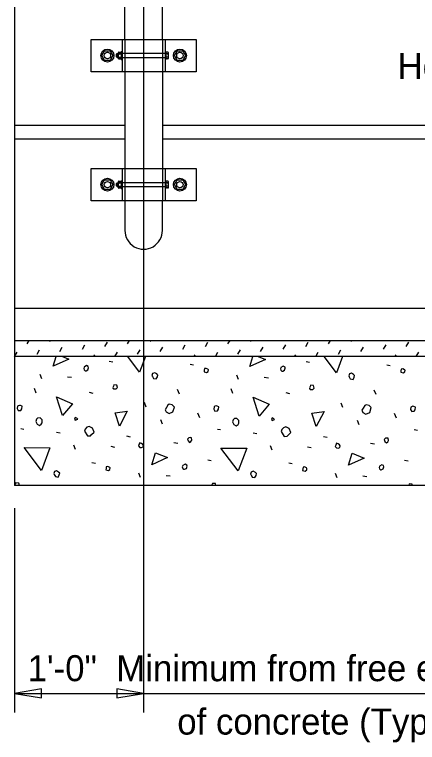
# Model space of a CAD drawing. Extents: x 0 to 41, y -96 to 25.
# Drawn here: x 3.62 to 6.74, y -84.64 to -79.01 of the extents above; entities that cross this region are included whole.
import ezdxf

# ---------------------------------------------------------------- set-up
doc = ezdxf.new("R2010")
doc.units = 0
for name, color, linetype in [('CL_Major', 7, 'Continuous'), ('Dimension', 7, 'Continuous'), ('Miscellaneous', 7, 'Continuous'), ('SteelMisc', 7, 'Continuous'), ('SteelMisc_h', 7, 'Continuous'), ('SupstrConc', 7, 'Continuous'), ('SupstrConc_h', 7, 'Continuous'), ('TextStructures', 7, 'Continuous')]:
    doc.layers.add(name, color=color, linetype=linetype)

msp = doc.modelspace()

# ---------------------------------------------------------------- linework, layer by layer
at = {"layer": 'CL_Major'}
msp.add_line((4.615, -70.4949), (4.615, -84.4122), dxfattribs=at)
at = {"layer": 'Dimension'}
for p, q in [((3.615, -82.8281), (3.615, -84.4122)), ((3.6151, -84.2642), (8.3895, -84.2642))]:
    msp.add_line(p, q, dxfattribs=at)
for points in [[(3.6151, -84.2641), (3.8233, -84.2994), (3.8233, -84.2288)], [(4.6151, -84.2641), (4.4068, -84.2288), (4.4068, -84.2993)]]:
    msp.add_lwpolyline(points, close=True, dxfattribs=at)
at = {"layer": 'Miscellaneous'}
for p, q in [((4.4075, -79.3301), (4.4075, -79.318)), ((4.4132, -79.3301), (4.4132, -79.318)), ((4.4075, -80.3301), (4.4075, -80.318)), ((4.4132, -80.3301), (4.4132, -80.318)), ((3.7123, -81.5575), (3.7283, -81.5298)), ((3.8873, -81.5381), (3.8921, -81.5298)), ((4.4901, -81.5575), (4.5062, -81.5298)), ((4.6651, -81.5381), (4.6699, -81.5298)), ((5.2679, -81.5575), (5.284, -81.5298)), ((5.4429, -81.5381), (5.4477, -81.5298)), ((6.0457, -81.5575), (6.0618, -81.5298)), ((6.2207, -81.5381), (6.2255, -81.5298)), ((3.9651, -81.6158), (3.9845, -81.5823)), ((4.1401, -81.5964), (4.1595, -81.5628)), ((4.3151, -81.577), (4.3345, -81.5434)), ((4.7429, -81.6158), (4.7623, -81.5823)), ((4.9179, -81.5964), (4.9373, -81.5628)), ((5.0929, -81.577), (5.1123, -81.5434)), ((5.5207, -81.6158), (5.5401, -81.5823)), ((5.6957, -81.5964), (5.7152, -81.5628)), ((5.8707, -81.577), (5.8902, -81.5434)), ((6.2985, -81.6158), (6.318, -81.5823)), ((6.4735, -81.5964), (6.493, -81.5628)), ((6.6485, -81.577), (6.668, -81.5434)), ((3.615, -81.6547), (3.6345, -81.6211)), ((3.7901, -81.6353), (3.8095, -81.6017)), ((4.2291, -81.6547), (4.2373, -81.6406)), ((4.3929, -81.6547), (4.4123, -81.6211)), ((4.5679, -81.6353), (4.5873, -81.6017)), ((5.0069, -81.6547), (5.0151, -81.6406)), ((5.1707, -81.6547), (5.1901, -81.6211)), ((5.3457, -81.6353), (5.3651, -81.6017)), ((5.7847, -81.6547), (5.7929, -81.6406)), ((5.9485, -81.6547), (5.9679, -81.6211)), ((6.1235, -81.6353), (6.143, -81.6017)), ((6.5626, -81.6547), (6.5708, -81.6406)), ((6.7263, -81.6547), (6.7458, -81.6211)), ((4.3489, -81.6901), (4.3754, -81.6954)), ((5.8727, -81.6936), (5.8992, -81.6989)), ((4.9746, -81.7148), (5.0012, -81.7201)), ((6.4985, -81.7184), (6.525, -81.7237)), ((3.8256, -81.828), (3.8132, -81.7944)), ((4.0254, -81.8121), (4.0572, -81.8156)), ((5.3494, -81.8315), (5.337, -81.7979)), ((5.5492, -81.8156), (5.581, -81.8191)), ((3.7832, -81.9376), (3.769, -81.9022)), ((4.8916, -81.9464), (4.8774, -81.9111)), ((5.307, -81.9411), (5.2928, -81.9058)), ((6.4154, -81.9499), (6.4012, -81.9146)), ((4.1933, -81.9305), (4.2216, -81.9376)), ((5.7171, -81.934), (5.7454, -81.9411)), ((4.6352, -82.0472), (4.6211, -82.0118)), ((6.1591, -82.0507), (6.1449, -82.0154)), ((5.0489, -82.1285), (5.0348, -82.0931)), ((4.7607, -82.1798), (4.7484, -82.1462)), ((6.2846, -82.1833), (6.2722, -82.1497)), ((6.5727, -82.132), (6.5586, -82.0967)), ((3.663, -82.2133), (3.6877, -82.2169)), ((3.9387, -82.2416), (3.9688, -82.2469)), ((5.1868, -82.2169), (5.2115, -82.2204)), ((5.4626, -82.2452), (5.4926, -82.2505)), ((6.7106, -82.2204), (6.7353, -82.224)), ((4.4832, -82.2699), (4.5115, -82.277)), ((6.007, -82.2735), (6.0353, -82.2805)), ((4.0872, -82.376), (4.0749, -82.3424)), ((4.3612, -82.3495), (4.3895, -82.3565)), ((4.8491, -82.3212), (4.8792, -82.3265)), ((5.611, -82.3795), (5.5987, -82.3459)), ((5.885, -82.353), (5.9133, -82.3601)), ((6.373, -82.3247), (6.403, -82.33)), ((3.615, -82.4555), (3.6152, -82.4555)), ((4.2145, -82.475), (4.241, -82.4803)), ((5.1125, -82.4538), (5.1391, -82.4591)), ((5.7383, -82.4785), (5.7648, -82.4838)), ((6.6363, -82.4573), (6.6629, -82.4626)), ((4.5893, -82.5916), (4.5769, -82.5581)), ((4.789, -82.5757), (4.8209, -82.5793)), ((6.1131, -82.5952), (6.1007, -82.5616)), ((6.3128, -82.5793), (6.3447, -82.5828))]:
    msp.add_line(p, q, dxfattribs=at)
for points in [[(3.914, -81.729), (3.9368, -81.6547)], [(3.9869, -81.6547), (4.036, -81.6742), (3.914, -81.729)], [(4.584, -81.7767), (4.4913, -81.6547)], [(4.6296, -81.6547), (4.584, -81.7767)], [(5.4378, -81.7325), (5.4617, -81.6547)], [(5.5018, -81.6547), (5.5598, -81.6777), (5.4378, -81.7325)], [(6.1078, -81.7802), (6.0124, -81.6547)], [(6.1547, -81.6547), (6.1078, -81.7802)], [(4.1615, -81.7643), (4.1685, -81.7643), (4.1827, -81.7573), (4.188, -81.7414), (4.1862, -81.7325), (4.1721, -81.7254), (4.1544, -81.736), (4.1509, -81.7467), (4.1544, -81.7573), (4.1615, -81.7643)], [(5.0825, -81.7732), (5.1019, -81.7785), (5.1143, -81.7696), (5.1161, -81.7573), (5.1125, -81.7537), (5.0984, -81.7467), (5.086, -81.7484), (5.0843, -81.7608), (5.0825, -81.7732)], [(5.6853, -81.7679), (5.6924, -81.7679), (5.7065, -81.7608), (5.7118, -81.7449), (5.71, -81.736), (5.6959, -81.729), (5.6782, -81.7396), (5.6747, -81.7502), (5.6782, -81.7608), (5.6853, -81.7679)], [(6.6063, -81.7767), (6.6257, -81.782), (6.6381, -81.7732), (6.6399, -81.7608), (6.6363, -81.7573), (6.6222, -81.7502), (6.6098, -81.752), (6.6081, -81.7643), (6.6063, -81.7767)], [(4.683, -81.8085), (4.6918, -81.8244), (4.713, -81.828), (4.7219, -81.8121), (4.7254, -81.7979), (4.7166, -81.7891), (4.7006, -81.7802), (4.6847, -81.7855), (4.6794, -81.8015), (4.683, -81.8085)], [(6.2068, -81.8121), (6.2156, -81.828), (6.2368, -81.8315), (6.2457, -81.8156), (6.2492, -81.8015), (6.2404, -81.7926), (6.2245, -81.7838), (6.2086, -81.7891), (6.2032, -81.805), (6.2068, -81.8121)], [(4.3807, -81.9058), (4.4019, -81.9058), (4.4125, -81.8951), (4.4072, -81.8757), (4.3842, -81.8739), (4.3807, -81.8845), (4.3754, -81.8934), (4.3807, -81.9058), (4.3771, -81.9022)], [(5.9045, -81.9093), (5.9257, -81.9093), (5.9363, -81.8987), (5.931, -81.8792), (5.908, -81.8775), (5.9045, -81.8881), (5.8992, -81.8969), (5.9045, -81.9093), (5.901, -81.9058)], [(3.9865, -82.1126), (3.9387, -81.9659), (4.0642, -82.0207), (3.9865, -82.1126)], [(5.5103, -82.1161), (5.4626, -81.9694), (5.5881, -82.0242), (5.5103, -82.1161)], [(3.6347, -82.0578), (3.6435, -82.0737), (3.663, -82.0719), (3.6718, -82.0596), (3.6736, -82.0401), (3.6612, -82.0348), (3.6524, -82.033), (3.6418, -82.0366), (3.6382, -82.0401), (3.6347, -82.0578)], [(4.789, -82.0843), (4.812, -82.0967), (4.8421, -82.0843), (4.8544, -82.0472), (4.8368, -82.0295), (4.8138, -82.0242), (4.8032, -82.0313), (4.7908, -82.0507), (4.782, -82.0666), (4.789, -82.0843)], [(5.1585, -82.0613), (5.1673, -82.0772), (5.1868, -82.0755), (5.1956, -82.0631), (5.1974, -82.0436), (5.185, -82.0383), (5.1762, -82.0366), (5.1656, -82.0401), (5.162, -82.0436), (5.1585, -82.0613)], [(6.3128, -82.0878), (6.3358, -82.1002), (6.3659, -82.0878), (6.3783, -82.0507), (6.3606, -82.033), (6.3376, -82.0277), (6.327, -82.0348), (6.3146, -82.0542), (6.3058, -82.0702), (6.3128, -82.0878)], [(4.4284, -82.1939), (4.3948, -82.0896), (4.4885, -82.0772), (4.4284, -82.1939)], [(5.9522, -82.1974), (5.9186, -82.0931), (6.0123, -82.0808), (5.9522, -82.1974)], [(6.6823, -82.0649), (6.6912, -82.0808), (6.7106, -82.079), (6.7194, -82.0666), (6.7212, -82.0472), (6.7088, -82.0419), (6.7, -82.0401), (6.6894, -82.0436), (6.6858, -82.0472), (6.6823, -82.0649)], [(3.7796, -82.1568), (3.7902, -82.178), (3.8079, -82.1886), (3.8221, -82.178), (3.8291, -82.1674), (3.8291, -82.1462), (3.8132, -82.1303), (3.7938, -82.132), (3.7849, -82.1409), (3.7796, -82.1568)], [(4.0855, -82.1479), (4.1049, -82.1391), (4.0978, -82.132), (4.0855, -82.1267), (4.0802, -82.1391), (4.0855, -82.1479)], [(5.3035, -82.1603), (5.3141, -82.1815), (5.3317, -82.1921), (5.3459, -82.1815), (5.353, -82.1709), (5.353, -82.1497), (5.337, -82.1338), (5.3176, -82.1356), (5.3088, -82.1444), (5.3035, -82.1603)], [(5.6093, -82.1515), (5.6287, -82.1426), (5.6217, -82.1356), (5.6093, -82.1303), (5.604, -82.1426), (5.6093, -82.1515)], [(4.1562, -82.2328), (4.1792, -82.2699), (4.2021, -82.2681), (4.211, -82.2593), (4.2304, -82.2399), (4.218, -82.2098), (4.1933, -82.1957), (4.1756, -82.2027), (4.1615, -82.2169), (4.1562, -82.2328)], [(5.68, -82.2363), (5.703, -82.2735), (5.7259, -82.2717), (5.7348, -82.2628), (5.7542, -82.2434), (5.7419, -82.2133), (5.7171, -82.1992), (5.6994, -82.2063), (5.6853, -82.2204), (5.68, -82.2363)], [(4.9605, -82.3088), (4.9711, -82.3194), (4.9817, -82.3123), (4.9888, -82.3017), (4.9853, -82.2841), (4.9764, -82.2823), (4.964, -82.2841), (4.9534, -82.2947), (4.9605, -82.3088)], [(6.4843, -82.3123), (6.4949, -82.3229), (6.5055, -82.3159), (6.5126, -82.3053), (6.5091, -82.2876), (6.5002, -82.2858), (6.4879, -82.2876), (6.4773, -82.2982), (6.4843, -82.3123)], [(3.8238, -82.5368), (3.6895, -82.3601), (3.8892, -82.3618), (3.8238, -82.5368)], [(4.5857, -82.3583), (4.5981, -82.3601), (4.6105, -82.3548), (4.614, -82.3442), (4.6087, -82.3353), (4.5981, -82.3283), (4.5857, -82.3229), (4.5787, -82.3371), (4.5751, -82.3477), (4.5857, -82.3583)], [(5.3476, -82.5404), (5.2133, -82.3636), (5.4131, -82.3654), (5.3476, -82.5404)], [(6.1096, -82.3618), (6.1219, -82.3636), (6.1343, -82.3583), (6.1378, -82.3477), (6.1325, -82.3389), (6.1219, -82.3318), (6.1096, -82.3265), (6.1025, -82.3406), (6.0989, -82.3512), (6.1096, -82.3618)], [(4.6777, -82.4927), (4.7059, -82.4007), (4.7996, -82.4379), (4.6777, -82.4927)], [(6.2015, -82.4962), (6.2298, -82.4043), (6.3235, -82.4414), (6.2015, -82.4962)], [(4.9252, -82.528), (4.9322, -82.528), (4.9464, -82.5209), (4.9517, -82.505), (4.9499, -82.4962), (4.9358, -82.4891), (4.9181, -82.4997), (4.9145, -82.5103), (4.9181, -82.5209), (4.9252, -82.528)], [(3.9228, -82.5687), (3.9317, -82.5846), (3.9529, -82.5881), (3.9617, -82.5722), (3.9653, -82.5581), (3.9564, -82.5492), (3.9405, -82.5404), (3.9246, -82.5457), (3.9193, -82.5616), (3.9228, -82.5687)], [(4.3223, -82.5333), (4.3418, -82.5386), (4.3542, -82.5298), (4.3559, -82.5174), (4.3524, -82.5139), (4.3383, -82.5068), (4.3259, -82.5086), (4.3241, -82.5209), (4.3223, -82.5333)], [(5.4466, -82.5722), (5.4555, -82.5881), (5.4767, -82.5916), (5.4855, -82.5757), (5.4891, -82.5616), (5.4802, -82.5528), (5.4643, -82.5439), (5.4484, -82.5492), (5.4431, -82.5651), (5.4466, -82.5722)], [(5.8462, -82.5368), (5.8656, -82.5422), (5.878, -82.5333), (5.8797, -82.5209), (5.8762, -82.5174), (5.8621, -82.5103), (5.8497, -82.5121), (5.8479, -82.5245), (5.8462, -82.5368)], [(6.449, -82.5315), (6.456, -82.5315), (6.4702, -82.5245), (6.4755, -82.5086), (6.4737, -82.4997), (6.4596, -82.4927), (6.4419, -82.5033), (6.4384, -82.5139), (6.4419, -82.5245), (6.449, -82.5315)], [(3.6522, -82.6547), (3.6471, -82.6358), (3.6241, -82.6341), (3.6205, -82.6447), (3.6152, -82.6535), (3.6158, -82.6547)], [(5.1751, -82.6547), (5.1709, -82.6394), (5.1479, -82.6376), (5.1444, -82.6482), (5.1404, -82.6547)], [(6.6979, -82.6547), (6.6947, -82.6429), (6.6717, -82.6411), (6.6682, -82.6518), (6.6664, -82.6547)]]:
    msp.add_lwpolyline(points, dxfattribs=at)
at = {"layer": 'SteelMisc'}
for p, q in [((4.4692, -79.1982), (4.4692, -78.7223)), ((4.7609, -79.1982), (4.7609, -78.7223)), ((4.2091, -79.1982), (5.021, -79.1982)), ((4.2091, -79.4482), (4.2091, -79.1982)), ((4.4484, -79.1982), (4.4484, -79.4482)), ((4.7817, -79.1982), (4.7817, -79.4482)), ((5.021, -79.1982), (5.021, -79.4482)), ((4.4047, -79.3152), (4.4103, -79.3086)), ((4.4047, -79.3329), (4.4047, -79.3152)), ((4.4103, -79.3086), (4.4168, -79.3086)), ((4.4103, -79.3385), (4.4103, -79.3086)), ((4.4168, -79.3053), (4.4168, -79.341)), ((4.4215, -79.3102), (4.4418, -79.3102)), ((4.4217, -79.2972), (4.4418, -79.2972)), ((4.4418, -79.2929), (4.4418, -79.3535)), ((4.4418, -79.2929), (4.4484, -79.2929)), ((4.4418, -79.2972), (4.4418, -79.3492)), ((4.788, -79.2929), (4.782, -79.2929)), ((4.788, -79.2929), (4.788, -79.3535)), ((4.8027, -79.2972), (4.788, -79.2972)), ((4.8028, -79.3102), (4.788, -79.3102)), ((4.8078, -79.3426), (4.8078, -79.3037)), ((4.4047, -79.3329), (4.4103, -79.3385)), ((4.4103, -79.3385), (4.4168, -79.3385)), ((4.4215, -79.3361), (4.4418, -79.3361)), ((4.4218, -79.3492), (4.4418, -79.3492)), ((4.4418, -79.3535), (4.4484, -79.3535)), ((4.788, -79.3535), (4.782, -79.3535)), ((4.8028, -79.3362), (4.788, -79.3362)), ((4.8027, -79.3492), (4.788, -79.3492)), ((5.021, -79.4482), (4.2091, -79.4482)), ((4.4692, -79.4482), (4.4692, -80.1982)), ((4.7609, -79.4482), (4.7609, -80.1982)), ((4.2091, -80.1982), (5.021, -80.1982)), ((4.2091, -80.4482), (4.2091, -80.1982)), ((4.4484, -80.1982), (4.4484, -80.4482)), ((4.7817, -80.1982), (4.7817, -80.4482)), ((5.021, -80.1982), (5.021, -80.4482)), ((4.4047, -80.3152), (4.4103, -80.3086)), ((4.4047, -80.3329), (4.4047, -80.3152)), ((4.4047, -80.3329), (4.4103, -80.3385)), ((4.4103, -80.3086), (4.4168, -80.3086)), ((4.4103, -80.3385), (4.4103, -80.3086)), ((4.4103, -80.3385), (4.4168, -80.3385)), ((4.4168, -80.3053), (4.4168, -80.341)), ((4.4215, -80.3102), (4.4418, -80.3102)), ((4.4215, -80.3361), (4.4418, -80.3361)), ((4.4217, -80.2972), (4.4418, -80.2972)), ((4.4418, -80.2929), (4.4418, -80.3535)), ((4.4418, -80.2929), (4.4484, -80.2929)), ((4.4418, -80.2972), (4.4418, -80.3492)), ((4.788, -80.2929), (4.782, -80.2929)), ((4.788, -80.2929), (4.788, -80.3535)), ((4.8027, -80.2972), (4.788, -80.2972)), ((4.8028, -80.3102), (4.788, -80.3102)), ((4.8028, -80.3362), (4.788, -80.3362)), ((4.8078, -80.3426), (4.8078, -80.3037)), ((4.4218, -80.3492), (4.4418, -80.3492)), ((4.4418, -80.3535), (4.4484, -80.3535)), ((4.788, -80.3535), (4.782, -80.3535)), ((4.8027, -80.3492), (4.788, -80.3492)), ((5.021, -80.4482), (4.2091, -80.4482)), ((4.4691, -80.4482), (4.4691, -80.6774)), ((4.7608, -80.6774), (4.7608, -80.4482))]:
    msp.add_line(p, q, dxfattribs=at)
for points in [[(4.3124, -79.2857), (4.3557, -79.2857), (4.3774, -79.3232), (4.3557, -79.3607), (4.3124, -79.3607), (4.2907, -79.3232)], [(4.8744, -79.2857), (4.9177, -79.2857), (4.9394, -79.3232), (4.9177, -79.3607), (4.8744, -79.3607), (4.8527, -79.3232)], [(4.3124, -80.2857), (4.3557, -80.2857), (4.3774, -80.3232), (4.3557, -80.3607), (4.3124, -80.3607), (4.2907, -80.3232)], [(4.8744, -80.2857), (4.9177, -80.2857), (4.9394, -80.3232), (4.9177, -80.3607), (4.8744, -80.3607), (4.8527, -80.3232)]]:
    msp.add_lwpolyline(points, close=True, dxfattribs=at)
for centre, radius in [((4.3341, -79.3232), 0.05), ((4.896, -79.3232), 0.05), ((4.3341, -79.3232), 0.025), ((4.896, -79.3232), 0.025), ((4.3341, -80.3232), 0.05), ((4.896, -80.3232), 0.05), ((4.3341, -80.3232), 0.025), ((4.896, -80.3232), 0.025)]:
    msp.add_circle(centre, radius, dxfattribs=at)
for centre, radius, start, end in [((4.4234, -79.3038), 0.00674, 104.4891, 254.1889), ((4.4363, -79.3232), 0.0196, 138.628, 221.372), ((4.801, -79.3038), 0.00673, 285.7823, 75.5404), ((4.7881, -79.3232), 0.0196, 318.628, 41.372), ((4.4234, -79.3427), 0.00673, 105.7823, 255.5404), ((4.801, -79.3427), 0.00674, 284.4891, 74.1889), ((4.4234, -80.3038), 0.00674, 104.4891, 254.1889), ((4.4363, -80.3232), 0.0196, 138.628, 221.372), ((4.4234, -80.3427), 0.00673, 105.7823, 255.5404), ((4.801, -80.3038), 0.00673, 285.7823, 75.5404), ((4.801, -80.3427), 0.00674, 284.4891, 74.1889), ((4.7881, -80.3232), 0.0196, 318.628, 41.372)]:
    msp.add_arc(centre, radius, start, end, dxfattribs=at)
msp.add_ellipse((4.615, -80.6774), major_axis=(0, 0.1458), ratio=0.999499, start_param=1.570796, end_param=4.712389, dxfattribs=at)
at = {"layer": 'SteelMisc_h'}
for p, q in [((4.4692, -79.1982), (4.4692, -79.4482)), ((4.7609, -79.1982), (4.7609, -79.4482)), ((4.7817, -79.3086), (4.4168, -79.3086)), ((4.4168, -79.3385), (4.7817, -79.3385)), ((4.4692, -80.1982), (4.4692, -80.4482)), ((4.7609, -80.1982), (4.7609, -80.4482)), ((4.7817, -80.3086), (4.4168, -80.3086)), ((4.4168, -80.3385), (4.7817, -80.3385))]:
    msp.add_line(p, q, dxfattribs=at)
at = {"layer": 'SupstrConc'}
for p, q in [((3.615, -78.8631), (3.615, -82.6547)), ((3.615, -79.8631), (4.4692, -79.8631)), ((4.7609, -79.8631), (14.4692, -79.8631)), ((3.615, -79.9673), (4.4692, -79.9673)), ((4.7609, -79.9673), (14.4692, -79.9673)), ((3.615, -81.5298), (16.002, -81.5298)), ((16.002, -81.6547), (3.615, -81.6547)), ((16.002, -82.6547), (3.615, -82.6547))]:
    msp.add_line(p, q, dxfattribs=at)
at = {"layer": 'SupstrConc_h'}
msp.add_line((3.615, -81.2797), (16.002, -81.2797), dxfattribs=at)

# ---------------------------------------------------------------- texts
at = {"layer": 'TextStructures'}
for s, p in [('Hog Rings @ 2\'-0" Centers', (6.5816, -79.5053)), ('1\'-0"  Minimum from free end ', (3.7161, -84.1697)), ('of concrete (Typ.)', (4.8754, -84.5833))]:
    msp.add_text(s, height=0.2016, dxfattribs=at).set_placement(p)

doc.saveas('drawing.dxf')
